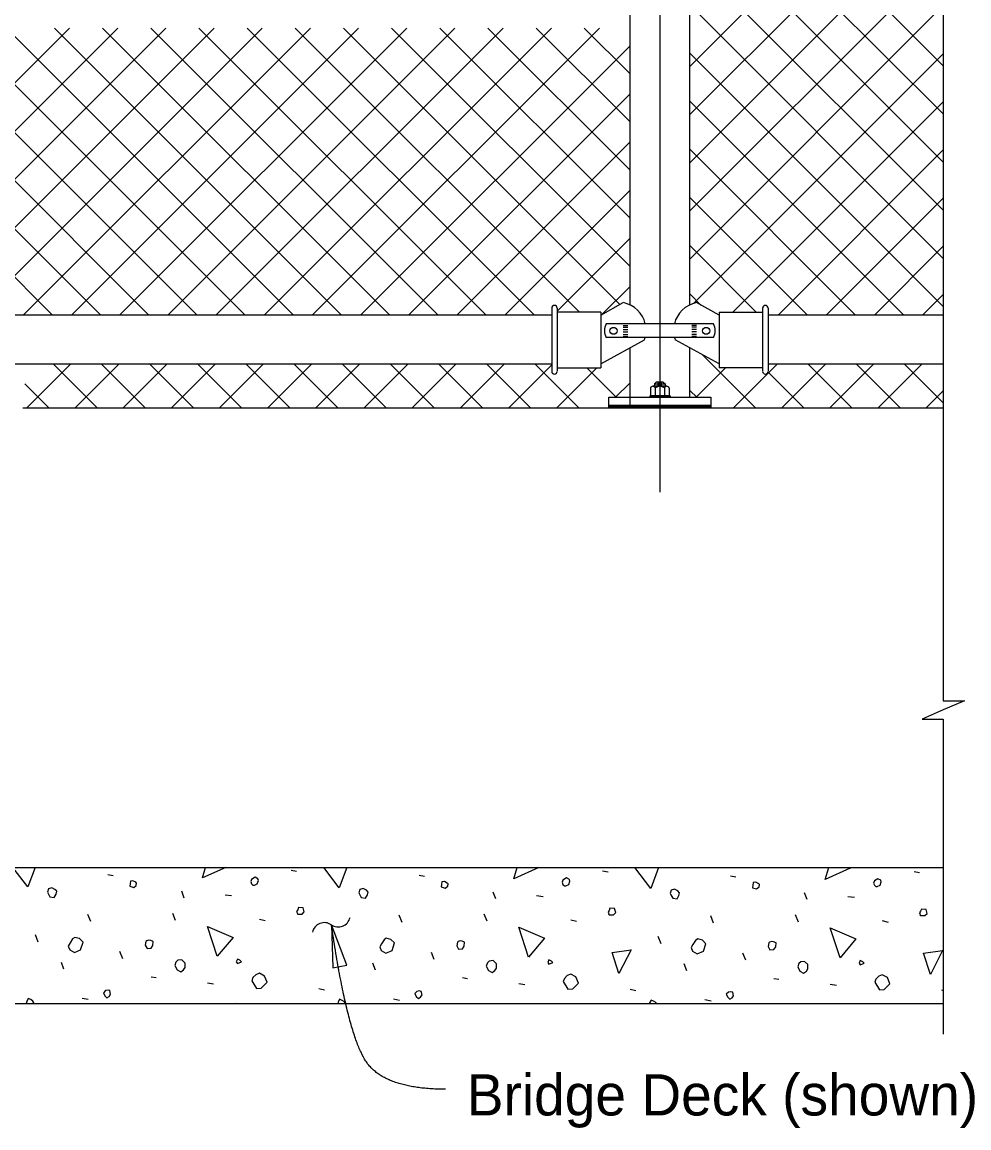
# Model space of a CAD drawing. Extents: x 0.4 to 38.5, y 1.2 to 25.4.
# Drawn here: x 18.95 to 23.59, y 13.43 to 18.85 of the extents above; entities that cross this region are included whole.
import ezdxf

# ---------------------------------------------------------------- set-up
doc = ezdxf.new("R2010")
doc.units = 0
for name, color, linetype in [('CL_Major', 7, 'Continuous'), ('Dimension', 7, 'Continuous'), ('Miscellaneous', 7, 'Continuous'), ('SteelMisc', 7, 'Continuous'), ('SupstrConc', 7, 'Continuous')]:
    doc.layers.add(name, color=color, linetype=linetype)

msp = doc.modelspace()

# ---------------------------------------------------------------- linework, layer by layer
at = {"layer": 'CL_Major'}
msp.add_line((22.075, 25.3255), (22.075, 16.5436), dxfattribs=at)
at = {"layer": 'Dimension'}
msp.add_line((22.075, 17.0171), (22.075, 17.0164), dxfattribs=at)
for points in [[(23.462, 20.0194), (23.462, 19.0017), (23.5654, 19.0017), (23.462, 18.9567), (23.3587, 18.9117), (23.462, 18.9117), (23.462, 16.9573)], [(23.462, 16.9573), (23.462, 15.5233), (23.5654, 15.5233), (23.462, 15.4783), (23.3587, 15.4333), (23.462, 15.4333), (23.462, 13.8908)]]:
    msp.add_lwpolyline(points, dxfattribs=at)
msp.add_lwpolyline([(20.4681, 14.4269), (20.4742, 14.2157), (20.5434, 14.2295)], close=True, dxfattribs=at)
for centre, start, end in [((20.501, 14.4756), 235.4525, 347.1798), ((20.4334, 14.3774), 55.4525, 167.1798)]:
    msp.add_arc(centre, 0.0596, start, end, dxfattribs=at)
msp.add_open_spline([(21.0265, 13.6215), (20.7379, 13.6215), (20.5488, 13.877), (20.468, 14.4269)], degree=2, dxfattribs=at)
at = {"layer": 'Miscellaneous'}
for p, q in [((16.0047, 20.5096), (19.104, 17.4104)), ((16.2404, 20.5096), (19.3397, 17.4104)), ((16.4761, 20.5096), (19.5754, 17.4104)), ((16.7118, 20.5096), (19.8111, 17.4104)), ((16.9475, 20.5096), (20.0468, 17.4104)), ((17.1832, 20.5096), (20.2825, 17.4104)), ((22.2209, 19.8723), (23.462, 18.6312)), ((22.2209, 18.628), (23.462, 19.8691)), ((22.2209, 19.6366), (23.462, 18.3955)), ((22.2209, 18.3923), (23.462, 19.6334)), ((22.2209, 19.4009), (23.462, 18.1598)), ((22.2209, 18.1566), (23.462, 19.3977)), ((22.2209, 19.1652), (23.462, 17.9241)), ((22.2209, 17.9209), (23.462, 19.162)), ((22.2209, 18.9295), (23.462, 17.6884)), ((22.2209, 17.6852), (23.4473, 18.9116)), ((17.7814, 17.4104), (19.1871, 18.8161)), ((18.0171, 17.4104), (19.4228, 18.8161)), ((18.2528, 17.4104), (19.6585, 18.8161)), ((18.4885, 17.4104), (19.8942, 18.8161)), ((18.7242, 17.4104), (20.1299, 18.8161)), ((18.9599, 17.4104), (20.3656, 18.8161)), ((19.1125, 18.8161), (20.5182, 17.4104)), ((19.1956, 17.4104), (20.6013, 18.8161)), ((19.3482, 18.8161), (20.7539, 17.4104)), ((19.4313, 17.4104), (20.837, 18.8161)), ((19.5839, 18.8161), (20.9896, 17.4104)), ((19.6671, 17.4104), (21.0727, 18.8161)), ((19.8196, 18.8161), (21.2253, 17.4104)), ((19.9028, 17.4104), (21.3084, 18.8161)), ((20.0553, 18.8161), (21.461, 17.4104)), ((20.1385, 17.4104), (21.5441, 18.8161)), ((20.291, 18.8161), (21.6813, 17.4258)), ((20.3742, 17.4104), (21.7798, 18.8161)), ((20.5267, 18.8161), (21.8796, 17.4632)), ((20.7624, 18.8161), (21.9292, 17.6492)), ((20.9981, 18.8161), (21.9292, 17.8849)), ((21.2338, 18.8161), (21.9292, 18.1206)), ((21.4695, 18.8161), (21.9292, 18.3563)), ((21.7052, 18.8161), (21.9292, 18.592)), ((20.6099, 17.4104), (21.9292, 18.7297)), ((22.2209, 18.6938), (23.462, 17.4527)), ((22.2398, 17.4684), (23.462, 18.6906)), ((20.8456, 17.4104), (21.9292, 18.494)), ((22.2209, 18.4581), (23.2686, 17.4104)), ((22.4329, 17.4258), (23.462, 18.4549)), ((21.0813, 17.4104), (21.9292, 18.2583)), ((22.2209, 18.2224), (23.0329, 17.4104)), ((22.6532, 17.4104), (23.462, 18.2192)), ((21.317, 17.4104), (21.9292, 18.0226)), ((22.2209, 17.9866), (22.7972, 17.4104)), ((22.8889, 17.4104), (23.462, 17.9835)), ((21.5725, 17.4302), (21.9292, 17.7869)), ((22.2209, 17.7509), (22.546, 17.4258)), ((23.1246, 17.4104), (23.462, 17.7478)), ((21.7935, 17.4155), (21.9292, 17.5512)), ((22.2209, 17.5152), (22.2761, 17.46)), ((23.3603, 17.4104), (23.462, 17.5121)), ((22.2843, 17.2162), (22.5432, 16.9573)), ((18.9782, 16.9573), (19.1918, 17.1708)), ((19.1078, 17.1708), (19.3214, 16.9573)), ((19.2139, 16.9573), (19.4275, 17.1708)), ((19.3436, 17.1708), (19.5571, 16.9573)), ((19.4496, 16.9573), (19.6632, 17.1708)), ((19.5793, 17.1708), (19.7928, 16.9573)), ((19.6853, 16.9573), (19.8989, 17.1708)), ((19.815, 17.1708), (20.0285, 16.9573)), ((19.921, 16.9573), (20.1346, 17.1708)), ((20.0507, 17.1708), (20.2642, 16.9573)), ((20.1567, 16.9573), (20.3703, 17.1708)), ((20.2864, 17.1708), (20.4999, 16.9573)), ((20.3924, 16.9573), (20.606, 17.1708)), ((20.5221, 17.1708), (20.7356, 16.9573)), ((20.6281, 16.9573), (20.8417, 17.1708)), ((20.7578, 17.1708), (20.9713, 16.9573)), ((20.8639, 16.9573), (21.0774, 17.1708)), ((20.9935, 17.1708), (21.207, 16.9573)), ((21.0996, 16.9573), (21.3131, 17.1708)), ((21.2292, 17.1708), (21.4427, 16.9573)), ((21.3353, 16.9573), (21.5457, 17.1677)), ((21.4649, 17.1708), (21.6784, 16.9573)), ((22.4357, 16.9573), (22.6493, 17.1708)), ((22.6714, 16.9573), (22.885, 17.1708)), ((22.8011, 17.1708), (23.0146, 16.9573)), ((22.9071, 16.9573), (23.1207, 17.1708)), ((23.0368, 17.1708), (23.2503, 16.9573)), ((23.1428, 16.9573), (23.3564, 17.1708)), ((23.2725, 17.1708), (23.462, 16.9813)), ((21.571, 16.9573), (21.7673, 17.1536)), ((21.7178, 17.1536), (21.862, 17.0093)), ((22.2521, 17.0093), (22.3963, 17.1536)), ((22.6044, 17.1318), (22.7789, 16.9573)), ((18.9682, 17.0747), (19.0857, 16.9573)), ((21.8587, 17.0093), (21.9292, 17.0798)), ((22.0638, 17.0788), (22.0846, 17.0788)), ((22.0638, 17.0691), (22.0846, 17.0691)), ((22.2241, 17.0406), (22.2554, 17.0093)), ((23.3785, 16.9573), (23.462, 17.0407)), ((21.825, 16.9642), (22.325, 16.9642)), ((21.825, 16.9607), (22.325, 16.9607)), ((19.3734, 14.6734), (19.3999, 14.6681)), ((20.2714, 14.6946), (20.2979, 14.6893)), ((20.8972, 14.6699), (20.9237, 14.6646)), ((21.7952, 14.6911), (21.8217, 14.6858)), ((23.319, 14.6876), (23.3456, 14.6823)), ((22.421, 14.6664), (22.4475, 14.6611)), ((19.7482, 14.5568), (19.7358, 14.5904)), ((19.9479, 14.5727), (19.9797, 14.5691)), ((21.272, 14.5532), (21.2596, 14.5868)), ((21.4717, 14.5691), (21.5036, 14.5656)), ((22.7958, 14.5497), (22.7834, 14.5833)), ((22.9955, 14.5656), (23.0274, 14.5621)), ((19.2903, 14.4419), (19.2762, 14.4772)), ((19.7057, 14.4472), (19.6916, 14.4825)), ((20.1159, 14.4542), (20.1441, 14.4472)), ((20.8141, 14.4383), (20.8, 14.4737)), ((21.2295, 14.4436), (21.2154, 14.479)), ((22.3379, 14.4348), (22.3238, 14.4701)), ((22.7534, 14.4401), (22.7392, 14.4754)), ((21.6397, 14.4507), (21.668, 14.4436)), ((23.1635, 14.4472), (23.1918, 14.4401)), ((19.034, 14.3411), (19.0198, 14.3765)), ((22.0816, 14.334), (22.0675, 14.3694)), ((19.4476, 14.2598), (19.4335, 14.2951)), ((20.9715, 14.2562), (20.9573, 14.2916)), ((19.1595, 14.2085), (19.1471, 14.2421)), ((20.6833, 14.205), (20.6709, 14.2386)), ((22.4953, 14.2527), (22.4811, 14.2881)), ((22.2071, 14.2014), (22.1947, 14.235)), ((19.5855, 14.1714), (19.6103, 14.1679)), ((19.8613, 14.1431), (19.8913, 14.1378)), ((21.1093, 14.1679), (21.1341, 14.1643)), ((21.3851, 14.1396), (21.4152, 14.1343)), ((22.6332, 14.1643), (22.6579, 14.1608)), ((22.9089, 14.136), (22.939, 14.1307)), ((20.4058, 14.1148), (20.4341, 14.1077)), ((21.9296, 14.1113), (21.9579, 14.1042)), ((23.4534, 14.1077), (23.462, 14.1056)), ((19.2479, 14.0671), (19.2779, 14.0618)), ((19.9981, 14.0406), (19.9974, 14.0423)), ((20.7717, 14.0636), (20.8017, 14.0583)), ((22.2955, 14.06), (22.3256, 14.0547))]:
    msp.add_line(p, q, dxfattribs=at)
msp.add_lwpolyline([(21.825, 16.9677), (22.325, 16.9677), (22.325, 16.9573), (21.825, 16.9573)], close=True, dxfattribs=at)
for points in [[(18.9827, 14.6116), (18.91, 14.7072)], [(19.0185, 14.7072), (18.9827, 14.6116)], [(19.8365, 14.6558), (19.8524, 14.7072)], [(19.9511, 14.7072), (19.8365, 14.6558)], [(20.5065, 14.608), (20.4311, 14.7072)], [(20.5436, 14.7072), (20.5065, 14.608)], [(21.3604, 14.6522), (21.3773, 14.7072)], [(21.4818, 14.7072), (21.4823, 14.707), (21.3604, 14.6522)], [(22.0303, 14.6045), (21.9523, 14.7072)], [(22.0687, 14.7072), (22.0303, 14.6045)], [(22.8842, 14.6487), (22.9022, 14.7072)], [(22.9967, 14.7072), (23.0062, 14.7035), (22.8842, 14.6487)], [(19.4812, 14.6151), (19.5007, 14.6098), (19.513, 14.6186), (19.5148, 14.631), (19.5113, 14.6345), (19.4971, 14.6416), (19.4848, 14.6398), (19.483, 14.6275), (19.4812, 14.6151)], [(20.084, 14.6204), (20.0911, 14.6204), (20.1052, 14.6275), (20.1106, 14.6434), (20.1088, 14.6522), (20.0946, 14.6593), (20.077, 14.6487), (20.0734, 14.6381), (20.077, 14.6275), (20.084, 14.6204)], [(21.005, 14.6116), (21.0245, 14.6063), (21.0369, 14.6151), (21.0386, 14.6275), (21.0351, 14.631), (21.021, 14.6381), (21.0086, 14.6363), (21.0068, 14.6239), (21.005, 14.6116)], [(21.6078, 14.6169), (21.6149, 14.6169), (21.6291, 14.6239), (21.6344, 14.6398), (21.6326, 14.6487), (21.6185, 14.6558), (21.6008, 14.6452), (21.5972, 14.6345), (21.6008, 14.6239), (21.6078, 14.6169)], [(22.5289, 14.608), (22.5483, 14.6027), (22.5607, 14.6116), (22.5624, 14.6239), (22.5589, 14.6275), (22.5448, 14.6345), (22.5324, 14.6328), (22.5306, 14.6204), (22.5289, 14.608)], [(23.1317, 14.6133), (23.1387, 14.6133), (23.1529, 14.6204), (23.1582, 14.6363), (23.1564, 14.6452), (23.1423, 14.6522), (23.1246, 14.6416), (23.1211, 14.631), (23.1246, 14.6204), (23.1317, 14.6133)], [(19.0817, 14.5797), (19.0905, 14.5638), (19.1118, 14.5603), (19.1206, 14.5762), (19.1241, 14.5904), (19.1153, 14.5992), (19.0994, 14.608), (19.0835, 14.6027), (19.0782, 14.5868), (19.0817, 14.5797)], [(20.6055, 14.5762), (20.6144, 14.5603), (20.6356, 14.5568), (20.6444, 14.5727), (20.648, 14.5868), (20.6391, 14.5957), (20.6232, 14.6045), (20.6073, 14.5992), (20.602, 14.5833), (20.6055, 14.5762)], [(22.1293, 14.5727), (22.1382, 14.5568), (22.1594, 14.5532), (22.1682, 14.5691), (22.1718, 14.5833), (22.1629, 14.5921), (22.147, 14.601), (22.1311, 14.5957), (22.1258, 14.5797), (22.1293, 14.5727)], [(20.3032, 14.479), (20.3244, 14.479), (20.3351, 14.4896), (20.3298, 14.509), (20.3068, 14.5108), (20.3032, 14.5002), (20.2979, 14.4914), (20.3032, 14.479), (20.2997, 14.4825)], [(21.8271, 14.4754), (21.8483, 14.4754), (21.8589, 14.4861), (21.8536, 14.5055), (21.8306, 14.5073), (21.8271, 14.4967), (21.8217, 14.4878), (21.8271, 14.4754), (21.8235, 14.479)], [(23.3509, 14.4719), (23.3721, 14.4719), (23.3827, 14.4825), (23.3774, 14.502), (23.3544, 14.5037), (23.3509, 14.4931), (23.3456, 14.4843), (23.3509, 14.4719), (23.3473, 14.4754)], [(19.909, 14.2722), (19.8613, 14.4189), (19.9868, 14.3641), (19.909, 14.2722)], [(21.4328, 14.2686), (21.3851, 14.4153), (21.5106, 14.3605), (21.4328, 14.2686)], [(22.9567, 14.2651), (22.9089, 14.4118), (23.0344, 14.357), (22.9567, 14.2651)], [(19.1878, 14.304), (19.2108, 14.2916), (19.2408, 14.304), (19.2532, 14.3411), (19.2355, 14.3588), (19.2125, 14.3641), (19.2019, 14.357), (19.1895, 14.3376), (19.1807, 14.3216), (19.1878, 14.304)], [(19.5572, 14.327), (19.5661, 14.311), (19.5855, 14.3128), (19.5944, 14.3252), (19.5961, 14.3446), (19.5838, 14.3499), (19.5749, 14.3517), (19.5643, 14.3482), (19.5608, 14.3446), (19.5572, 14.327)], [(20.7116, 14.3004), (20.7346, 14.2881), (20.7646, 14.3004), (20.777, 14.3376), (20.7593, 14.3552), (20.7363, 14.3605), (20.7257, 14.3535), (20.7134, 14.334), (20.7045, 14.3181), (20.7116, 14.3004)], [(21.0811, 14.3234), (21.0899, 14.3075), (21.1093, 14.3093), (21.1182, 14.3216), (21.1199, 14.3411), (21.1076, 14.3464), (21.0987, 14.3482), (21.0881, 14.3446), (21.0846, 14.3411), (21.0811, 14.3234)], [(22.2354, 14.2969), (22.2584, 14.2845), (22.2884, 14.2969), (22.3008, 14.334), (22.2831, 14.3517), (22.2602, 14.357), (22.2495, 14.3499), (22.2372, 14.3305), (22.2283, 14.3146), (22.2354, 14.2969)], [(22.6049, 14.3199), (22.6137, 14.304), (22.6332, 14.3057), (22.642, 14.3181), (22.6438, 14.3376), (22.6314, 14.3429), (22.6225, 14.3446), (22.6119, 14.3411), (22.6084, 14.3376), (22.6049, 14.3199)], [(21.8748, 14.1873), (21.8412, 14.2916), (21.9349, 14.304), (21.8748, 14.1873)], [(23.3986, 14.1838), (23.365, 14.2881), (23.4587, 14.3004), (23.3986, 14.1838)], [(19.7022, 14.228), (19.7128, 14.2067), (19.7305, 14.1961), (19.7446, 14.2067), (19.7517, 14.2174), (19.7517, 14.2386), (19.7358, 14.2545), (19.7163, 14.2527), (19.7075, 14.2439), (19.7022, 14.228)], [(20.008, 14.2368), (20.0275, 14.2456), (20.0204, 14.2527), (20.008, 14.258), (20.0027, 14.2456), (20.008, 14.2368)], [(21.226, 14.2244), (21.2366, 14.2032), (21.2543, 14.1926), (21.2684, 14.2032), (21.2755, 14.2138), (21.2755, 14.235), (21.2596, 14.2509), (21.2402, 14.2492), (21.2313, 14.2403), (21.226, 14.2244)], [(21.5318, 14.2333), (21.5513, 14.2421), (21.5442, 14.2492), (21.5318, 14.2545), (21.5265, 14.2421), (21.5318, 14.2333)], [(22.7498, 14.2209), (22.7604, 14.1997), (22.7781, 14.1891), (22.7923, 14.1997), (22.7993, 14.2103), (22.7993, 14.2315), (22.7834, 14.2474), (22.764, 14.2456), (22.7551, 14.2368), (22.7498, 14.2209)], [(23.0556, 14.2297), (23.0751, 14.2386), (23.068, 14.2456), (23.0556, 14.2509), (23.0503, 14.2386), (23.0556, 14.2297)], [(20.0787, 14.1519), (20.1017, 14.1148), (20.1247, 14.1166), (20.1335, 14.1254), (20.153, 14.1449), (20.1406, 14.1749), (20.1159, 14.1891), (20.0982, 14.182), (20.084, 14.1679), (20.0787, 14.1519)], [(21.6025, 14.1484), (21.6255, 14.1113), (21.6485, 14.1131), (21.6573, 14.1219), (21.6768, 14.1413), (21.6644, 14.1714), (21.6397, 14.1855), (21.622, 14.1785), (21.6078, 14.1643), (21.6025, 14.1484)], [(23.1264, 14.1449), (23.1493, 14.1077), (23.1723, 14.1095), (23.1812, 14.1184), (23.2006, 14.1378), (23.1882, 14.1679), (23.1635, 14.182), (23.1458, 14.1749), (23.1317, 14.1608), (23.1264, 14.1449)], [(19.3592, 14.0795), (19.3699, 14.0689), (19.3805, 14.0759), (19.3875, 14.0865), (19.384, 14.1042), (19.3752, 14.106), (19.3628, 14.1042), (19.3522, 14.0936), (19.3592, 14.0795)], [(20.8831, 14.0759), (20.8937, 14.0653), (20.9043, 14.0724), (20.9113, 14.083), (20.9078, 14.1007), (20.899, 14.1024), (20.8866, 14.1007), (20.876, 14.0901), (20.8831, 14.0759)], [(22.4069, 14.0724), (22.4175, 14.0618), (22.4281, 14.0689), (22.4352, 14.0795), (22.4316, 14.0971), (22.4228, 14.0989), (22.4104, 14.0971), (22.3998, 14.0865), (22.4069, 14.0724)], [(19.0116, 14.0406), (19.0128, 14.0441), (19.0075, 14.0529), (18.9969, 14.06), (18.9845, 14.0653), (18.9774, 14.0512), (18.9739, 14.0406)], [(20.5366, 14.0406), (20.5313, 14.0494), (20.5207, 14.0565), (20.5083, 14.0618), (20.5012, 14.0476), (20.4989, 14.0406)], [(22.0583, 14.0406), (22.0551, 14.0459), (22.0445, 14.0529), (22.0321, 14.0583), (22.025, 14.0441), (22.0239, 14.0406)]]:
    msp.add_lwpolyline(points, dxfattribs=at)
at = {"layer": 'SteelMisc'}
for p, q in [((21.9292, 17.4606), (21.9292, 22.6681)), ((22.2209, 17.4606), (22.2209, 22.668)), ((21.5457, 17.4454), (21.5457, 17.1357)), ((21.5725, 17.4454), (21.5725, 17.1357)), ((21.7855, 17.4111), (21.8963, 17.4724)), ((22.3646, 17.4111), (22.2537, 17.4724)), ((22.5775, 17.4454), (22.5775, 17.1357)), ((22.6044, 17.4454), (22.6044, 17.1357)), ((21.5457, 17.4104), (12.6044, 17.4104)), ((21.7855, 17.4258), (21.5725, 17.4258)), ((21.7855, 17.4258), (21.7855, 17.1536)), ((22.3646, 17.4258), (22.3646, 17.1536)), ((22.3646, 17.4258), (22.5775, 17.4258)), ((23.462, 17.4104), (22.6044, 17.4104)), ((22.3374, 17.3685), (21.8126, 17.3685)), ((21.895, 17.3607), (21.9185, 17.3607)), ((21.895, 17.3511), (21.9185, 17.3511)), ((21.895, 17.3402), (21.9185, 17.3402)), ((21.895, 17.3285), (21.9185, 17.3285)), ((22.255, 17.3607), (22.2316, 17.3607)), ((22.255, 17.3511), (22.2316, 17.3511)), ((22.255, 17.3402), (22.2316, 17.3402)), ((22.255, 17.3285), (22.2316, 17.3285)), ((21.7855, 17.1717), (21.9994, 17.2902)), ((22.3374, 17.3007), (21.8126, 17.3007)), ((21.895, 17.3167), (21.9185, 17.3167)), ((21.895, 17.3069), (21.9185, 17.3069)), ((22.3646, 17.1717), (22.1506, 17.2902)), ((22.255, 17.3167), (22.2316, 17.3167)), ((22.255, 17.3069), (22.2316, 17.3069)), ((21.9292, 16.9573), (21.9292, 17.2513)), ((22.2209, 17.0093), (22.2209, 17.2513)), ((21.5457, 17.1708), (12.6044, 17.1708)), ((23.462, 17.1708), (22.6044, 17.1708)), ((21.5725, 17.1536), (21.7855, 17.1536)), ((22.5775, 17.1536), (22.3646, 17.1536)), ((22.0296, 17.054), (22.0296, 17.0164)), ((22.1091, 17.0627), (22.0409, 17.0627)), ((22.0589, 17.0837), (22.0492, 17.074)), ((22.0492, 17.074), (22.0492, 17.0627)), ((22.0492, 17.074), (22.1007, 17.074)), ((22.0523, 17.0543), (22.0523, 17.0164)), ((22.0589, 17.0837), (22.0894, 17.0837)), ((22.0894, 17.0837), (22.1007, 17.074)), ((22.0977, 17.0543), (22.0977, 17.0164)), ((22.1007, 17.074), (22.1007, 17.0627)), ((22.1204, 17.054), (22.1204, 17.0164)), ((22.0253, 17.0164), (22.0253, 17.0093)), ((22.0253, 17.0164), (22.1247, 17.0164)), ((22.1204, 17.0164), (22.0296, 17.0164)), ((22.1247, 17.0164), (22.1247, 17.0093)), ((21.9552, 16.9677), (22.1948, 16.9677))]:
    msp.add_line(p, q, dxfattribs=at)
msp.add_lwpolyline([(21.825, 17.0093), (22.325, 17.0093), (22.325, 16.9677), (21.825, 16.9677)], close=True, dxfattribs=at)
for centre, radius, start, end in [((21.5592, 17.4453), 0.0134, 0, 180), ((22.5909, 17.4453), 0.0134, 0, 180), ((21.5592, 17.1355), 0.0134, 180, 0), ((22.5909, 17.1355), 0.0134, 180, 0), ((22.041, 17.0509), 0.0118, 16.5986, 164.7005), ((22.075, 17.028), 0.0347, 49.2015, 130.7985), ((22.109, 17.051), 0.0118, 15.1506, 163.5042)]:
    msp.add_arc(centre, radius, start, end, dxfattribs=at)
for centre, major_axis, start_param, end_param in [((21.8618, 17.3365), (0.146, 0), 0.231126, 1.331255), ((22.2882, 17.3365), (-0.146, 0), 4.95193, 6.05206), ((21.8818, 17.3345), (-0.0776, 0), 5.810211, 6.75616), ((22.2683, 17.3345), (0.0776, 0), 5.810211, 6.75616), ((21.8618, 17.3365), (0.146, 0), 5.947976, 6.024627), ((22.2882, 17.3365), (-0.146, 0), 0.258558, 0.335209)]:
    msp.add_ellipse(centre, major_axis=major_axis, ratio=0.957868, start_param=start_param, end_param=end_param, dxfattribs=at)
for centre, major_axis in [((21.8485, 17.334), (0.0178, 0)), ((22.3016, 17.334), (-0.0178, 0))]:
    msp.add_ellipse(centre, major_axis=major_axis, ratio=0.957868, dxfattribs=at)
at = {"layer": 'SupstrConc'}
for p, q in [((18.9581, 16.9573), (23.462, 16.9573)), ((0.6881, 14.7072), (23.462, 14.7072)), ((0.6881, 14.0406), (23.462, 14.0406))]:
    msp.add_line(p, q, dxfattribs=at)

# ---------------------------------------------------------------- texts
at = {"layer": 'Dimension'}
msp.add_text('Bridge Deck (shown)', height=0.2016, dxfattribs=at).set_placement((21.1302, 13.4931))

doc.saveas('drawing.dxf')
